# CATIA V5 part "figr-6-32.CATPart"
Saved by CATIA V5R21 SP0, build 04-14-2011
Part number: Part1
Bounding box of the stored display mesh (mm): x -36 to 36, y -66.608 to 66.608, z -13.545 to 13.545
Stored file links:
  D:\CATIA V5R21 E-RESOURCES\CATIA-V5R21\catia-v5r21-prt\c06-catia-v5r21-prt\c06-catia-v5r21-figr-6-32.CATPart
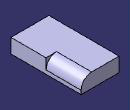
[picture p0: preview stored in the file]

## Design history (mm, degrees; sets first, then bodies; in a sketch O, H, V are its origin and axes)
Body1 (main body)
  Sketch1 on yz-plane, origin (0, 0, 0), H (0, 1, 0), V (0, 0, 1)
    line L1 (-66.6077, 13.5449) -> (66.6077, 13.5449)
    line L2 (66.6077, 13.5449) -> (66.6077, -13.5449)
    line L3 (66.6077, -13.5449) -> (-66.6077, -13.5449)
    line L4 (-66.6077, -13.5449) -> (-66.6077, 13.5449)
    axis line L5 (66.6077, -13.5449) -> (-66.6077, 13.5449)
    horizontal: L1 H, L3 H
    vertical: L2 V, L4 V
    midpoint: O L5
  Pad1: profile Sketch1, direction (1, 0, 0), length 36, mirrored extent
  Fillet1: radius 20, on edge [face of Pad1 | face of Pad1]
